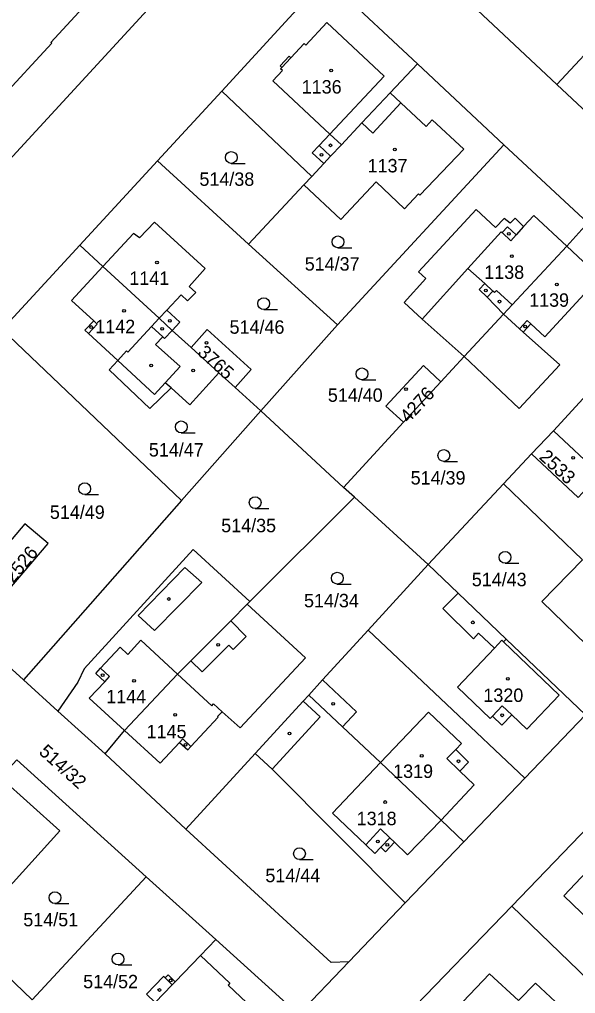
# Model space of a CAD drawing. Extents: x -679220 to -673243, y -1075091 to -1066557.
# Drawn here: x -675883.3 to -675812.8, y -1071990 to -1071866.6 of the extents above; entities that cross this region are included whole.
import ezdxf

# ---------------------------------------------------------------- set-up
doc = ezdxf.new("R2010")
doc.units = 0
for name, color, linetype in [('Hranice parcel', 7, 'Continuous'), ('Parcelní čísla', 7, 'Continuous'), ('Vnitřní kresba', 7, 'Continuous'), ('Značky budov', 7, 'Continuous'), ('Značky kultur', 7, 'Continuous')]:
    doc.layers.add(name, color=color, linetype=linetype)

msp = doc.modelspace()

# ---------------------------------------------------------------- linework, layer by layer
at = {"layer": 'Hranice parcel'}
for p, q in [((-675901.1, -1071902.37), (-675855.72, -1071853.08)), ((-675845.47, -1071862.48), (-675857.63, -1071875.7)), ((-675826.57, -1071864.15), (-675815.16, -1071874.86)), ((-675836.28, -1071875.93), (-675832.83, -1071872.25)), ((-675821.85, -1071882.53), (-675832.83, -1071872.25)), ((-675815.16, -1071874.86), (-675804.58, -1071884.78)), ((-675857.63, -1071875.7), (-675865.78, -1071884.56)), ((-675857.63, -1071875.7), (-675846.23, -1071886.54)), ((-675842.97, -1071905.34), (-675821.85, -1071882.53)), ((-675811.23, -1071892.4), (-675821.85, -1071882.53)), ((-675865.78, -1071884.56), (-675875.64, -1071895.21)), ((-675865.78, -1071884.56), (-675854.23, -1071895.09)), ((-675846.23, -1071886.54), (-675847.22, -1071887.6)), ((-675847.22, -1071887.6), (-675854.23, -1071895.09)), ((-675811.23, -1071892.4), (-675813.9, -1071895.36)), ((-675875.64, -1071895.21), (-675885.45, -1071905.91)), ((-675875.64, -1071895.21), (-675872.69, -1071897.92)), ((-675854.23, -1071895.09), (-675842.97, -1071905.34)), ((-675842.97, -1071905.34), (-675852.69, -1071916.2)), ((-675885.45, -1071905.91), (-675862.74, -1071927.57)), ((-675861.5, -1071908.21), (-675863.91, -1071906.02)), ((-675857.99, -1071911.4), (-675861.5, -1071908.21)), ((-675826.9, -1071909.35), (-675829.85, -1071912.55)), ((-675836.82, -1071915.62), (-675832.07, -1071910.45)), ((-675832.07, -1071910.45), (-675829.85, -1071912.55)), ((-675855.95, -1071913.25), (-675857.99, -1071911.4)), ((-675855.95, -1071913.25), (-675852.69, -1071916.2)), ((-675829.85, -1071912.55), (-675834.59, -1071917.67)), ((-675834.59, -1071917.67), (-675836.82, -1071915.62)), ((-675815.59, -1071918.73), (-675811.79, -1071914.67)), ((-675852.69, -1071916.2), (-675862.74, -1071927.57)), ((-675842.21, -1071925.93), (-675852.69, -1071916.2)), ((-675834.59, -1071917.67), (-675842.21, -1071925.93)), ((-675815.59, -1071918.73), (-675818.35, -1071921.68)), ((-675821.9, -1071925.48), (-675818.35, -1071921.68)), ((-675831.46, -1071935.7), (-675821.9, -1071925.48)), ((-675811.91, -1071935.09), (-675821.9, -1071925.48)), ((-675840.82, -1071927.14), (-675842.21, -1071925.93)), ((-675862.74, -1071927.57), (-675882.76, -1071950.27)), ((-675840.82, -1071927.14), (-675854.05, -1071940.37)), ((-675831.46, -1071935.7), (-675840.82, -1071927.14)), ((-675831.46, -1071935.7), (-675839.07, -1071944)), ((-675854.41, -1071940.72), (-675854.05, -1071940.37)), ((-675819.22, -1071962.75), (-675839.07, -1071944)), ((-675878.42, -1071954.27), (-675882.76, -1071950.27)), ((-675878.42, -1071954.27), (-675872.41, -1071959.68)), ((-675819.22, -1071962.75), (-675811.53, -1071954.74)), ((-675872.41, -1071959.68), (-675869.95, -1071956.71)), ((-675862.19, -1071969.22), (-675872.41, -1071959.68)), ((-675862.19, -1071969.22), (-675853.4, -1071959.63)), ((-675883.62, -1071960.42), (-675867.2, -1071975.24)), ((-675826.96, -1071970.82), (-675819.22, -1071962.75)), ((-675811.14, -1071968.85), (-675820.87, -1071978.95)), ((-675834.38, -1071978.55), (-675826.96, -1071970.82)), ((-675881.66, -1071990.83), (-675867.2, -1071975.24)), ((-675867.2, -1071975.24), (-675858.37, -1071983.2)), ((-675841.54, -1071986.02), (-675834.38, -1071978.55)), ((-675820.87, -1071978.95), (-675834.25, -1071992.83)), ((-675820.87, -1071978.95), (-675806.12, -1071993.2)), ((-675890.64, -1071982.25), (-675881.66, -1071990.83)), ((-675848.93, -1071993.73), (-675841.54, -1071986.02))]:
    msp.add_line(p, q, dxfattribs=at)
for points in [[(-675879.3, -1071869.55), (-675867.15, -1071856.4), (-675878.15, -1071846.32), (-675881.81, -1071850.32), (-675878.64, -1071853.22), (-675887.1, -1071862.37), (-675891.64, -1071858.18), (-675898.1, -1071865.18), (-675893.57, -1071869.37), (-675900, -1071876.33), (-675900.67, -1071875.72), (-675902.04, -1071877.21), (-675902.65, -1071876.64), (-675903.4, -1071877.45), (-675905.25, -1071875.74), (-675908.95, -1071879.75), (-675898.03, -1071889.82), (-675885.83, -1071876.61), (-675885.72, -1071876.72), (-675879.19, -1071869.65), (-675879.3, -1071869.55)], [(-675799.09, -1071857.6), (-675802.4, -1071861.16), (-675815.16, -1071874.86)], [(-675832.83, -1071872.25), (-675843.33, -1071862.41), (-675845.47, -1071862.48)], [(-675847.22, -1071887.6), (-675842.54, -1071891.96), (-675838.04, -1071887.22), (-675834.47, -1071890.62), (-675832.68, -1071888.72), (-675832.5, -1071888.9), (-675826.93, -1071883.08), (-675830.94, -1071879.34), (-675831.73, -1071880.18), (-675834.93, -1071877.19), (-675836.28, -1071875.93)], [(-675846.23, -1071886.54), (-675844.7, -1071884.9), (-675843.83, -1071883.97), (-675842.46, -1071882.51), (-675839.86, -1071879.74), (-675836.28, -1071875.93)], [(-675813.9, -1071895.36), (-675818.07, -1071891.47), (-675819.37, -1071892.88), (-675820.45, -1071891.79), (-675821.07, -1071892.46), (-675821.83, -1071891.83), (-675822.92, -1071893.01), (-675825.37, -1071890.69), (-675832.67, -1071898.6), (-675831.75, -1071899.45), (-675834.5, -1071902.5), (-675832.21, -1071904.61), (-675826.9, -1071909.35)], [(-675863.91, -1071906.02), (-675862.96, -1071904.98), (-675864.6, -1071903.45), (-675862.76, -1071901.53), (-675861.96, -1071902.26), (-675860.93, -1071901.22), (-675861.78, -1071900.46), (-675859.72, -1071898.19), (-675866.15, -1071892.33), (-675868.07, -1071894.31), (-675868.83, -1071893.73), (-675872.69, -1071897.92)], [(-675826.9, -1071909.35), (-675821.91, -1071903.95), (-675820.83, -1071902.79), (-675813.9, -1071895.36)], [(-675826.9, -1071909.35), (-675819.92, -1071915.91), (-675814.78, -1071910.39), (-675819.43, -1071906.26), (-675818.44, -1071905.2), (-675816.67, -1071906.85), (-675809.7, -1071899.29), (-675813.9, -1071895.36)], [(-675872.69, -1071897.92), (-675876.67, -1071902.23), (-675873.86, -1071904.83), (-675874.98, -1071905.99), (-675874.53, -1071906.4), (-675870.81, -1071909.84), (-675871.89, -1071911.01), (-675866.74, -1071915.93), (-675864.06, -1071913.32), (-675861.68, -1071915.47), (-675857.99, -1071911.4)], [(-675872.69, -1071897.92), (-675865.57, -1071904.49), (-675863.91, -1071906.02)], [(-675861.5, -1071908.21), (-675859.49, -1071905.93), (-675853.9, -1071910.96), (-675855.95, -1071913.25)], [(-675818.35, -1071921.68), (-675812.45, -1071927.19), (-675809.7, -1071924.24), (-675815.59, -1071918.73)], [(-675882.76, -1071950.27), (-675905.4, -1071929.7), (-675905.43, -1071927.64)], [(-675887.68, -1071936.49), (-675884.73, -1071939.01), (-675879.65, -1071933.04), (-675882.58, -1071930.53), (-675887.68, -1071936.49)], [(-675854.05, -1071940.37), (-675861.26, -1071933.8), (-675875.08, -1071948.91), (-675875.87, -1071950.6), (-675878.42, -1071954.27)], [(-675811.91, -1071935.09), (-675817.04, -1071940.36), (-675810, -1071947.2), (-675804.84, -1071941.89)], [(-675811.53, -1071954.74), (-675821.58, -1071945.14), (-675827.67, -1071939.33), (-675831.46, -1071935.7)], [(-675869.95, -1071956.71), (-675863.24, -1071949.57), (-675861.55, -1071947.87), (-675856.49, -1071942.81), (-675854.41, -1071940.72)], [(-675869.95, -1071956.71), (-675865.42, -1071960.85), (-675862.97, -1071958.21), (-675861.94, -1071959.17), (-675861.54, -1071958.73), (-675858.07, -1071955.01), (-675858.15, -1071954.93), (-675857.58, -1071954.34), (-675855.28, -1071956.35), (-675847, -1071947.5), (-675854.41, -1071940.72)], [(-675839.07, -1071944), (-675844.85, -1071950.31), (-675846.61, -1071952.22)], [(-675846.61, -1071952.22), (-675847.32, -1071953), (-675853.4, -1071959.63)], [(-675826.96, -1071970.82), (-675829.83, -1071968.06), (-675837.49, -1071960.77), (-675842.33, -1071956.24), (-675846.61, -1071952.22)], [(-675853.4, -1071959.63), (-675851.26, -1071961.6), (-675834.38, -1071978.55)], [(-675890.64, -1071982.25), (-675886.07, -1071976.54), (-675885.24, -1071977.29), (-675878.14, -1071969.43), (-675885.7, -1071962.68), (-675883.62, -1071960.42)], [(-675841.54, -1071986.02), (-675843.78, -1071986.09), (-675862.19, -1071969.22)], [(-675808.43, -1071971.5), (-675814.28, -1071977.65), (-675808.71, -1071982.95), (-675807.04, -1071984.47)], [(-675858.37, -1071983.2), (-675860.31, -1071985.21), (-675863.53, -1071988.54), (-675864.44, -1071987.66), (-675864.81, -1071988.05), (-675865, -1071987.87), (-675867.17, -1071990.12), (-675866.07, -1071991.18), (-675867.74, -1071992.91), (-675871.32, -1071997.22), (-675873.06, -1071999.04)], [(-675848.93, -1071993.73), (-675849.01, -1071991.65), (-675858.37, -1071983.2)], [(-675826.28, -1071996.85), (-675826.93, -1071997.58), (-675826.68, -1071997.8), (-675827.77, -1071998.48), (-675825.66, -1072000.44), (-675825.06, -1071999.32), (-675824.82, -1071999.54), (-675824.2, -1071998.83), (-675820.87, -1072001.92), (-675815.03, -1071995.66), (-675816.85, -1071993.94), (-675814.7, -1071991.66), (-675817.85, -1071988.7), (-675820, -1071990.89), (-675823.68, -1071987.53), (-675829.61, -1071993.73), (-675826.28, -1071996.85)]]:
    msp.add_lwpolyline(points, dxfattribs=at)
at = {"layer": 'Vnitřní kresba'}
for p, q in [((-675846.96, -1071869.88), (-675844.29, -1071867.01)), ((-675837.06, -1071873.8), (-675844.29, -1071867.01)), ((-675848.87, -1071871.49), (-675847.18, -1071869.68)), ((-675847.18, -1071869.68), (-675846.96, -1071869.88)), ((-675850.22, -1071872.5), (-675849.09, -1071871.28)), ((-675849.09, -1071871.28), (-675848.87, -1071871.49)), ((-675850, -1071872.71), (-675850.22, -1071872.5)), ((-675850, -1071872.71), (-675848.87, -1071871.49)), ((-675851.16, -1071874.39), (-675849.95, -1071873.09)), ((-675850.17, -1071872.89), (-675850, -1071872.71)), ((-675849.95, -1071873.09), (-675850.17, -1071872.89)), ((-675843.92, -1071881.15), (-675851.16, -1071874.39)), ((-675837.06, -1071873.8), (-675843.92, -1071881.15)), ((-675838.48, -1071881.06), (-675834.93, -1071877.19)), ((-675839.86, -1071879.74), (-675838.48, -1071881.06)), ((-675845.29, -1071882.61), (-675843.92, -1071881.15)), ((-675843.92, -1071881.15), (-675842.46, -1071882.51)), ((-675846.16, -1071883.53), (-675845.29, -1071882.61)), ((-675844.7, -1071884.9), (-675846.16, -1071883.53)), ((-675845.29, -1071882.61), (-675843.83, -1071883.97)), ((-675822.09, -1071893.64), (-675821.41, -1071892.9)), ((-675821.41, -1071892.9), (-675820.29, -1071893.91)), ((-675819.37, -1071892.88), (-675820.29, -1071893.91)), ((-675826.45, -1071898.19), (-675822.2, -1071893.54)), ((-675822.2, -1071893.54), (-675822.09, -1071893.64)), ((-675822.09, -1071893.64), (-675820.97, -1071894.66)), ((-675820.97, -1071894.66), (-675820.29, -1071893.91)), ((-675826.45, -1071898.19), (-675832.21, -1071904.61)), ((-675824.29, -1071900.08), (-675826.45, -1071898.19)), ((-675825.01, -1071900.85), (-675824.29, -1071900.08)), ((-675823.98, -1071901.81), (-675825.01, -1071900.85)), ((-675824.29, -1071900.08), (-675823.27, -1071901.04)), ((-675823.27, -1071901.04), (-675823.98, -1071901.81)), ((-675821.91, -1071903.95), (-675823.98, -1071901.81)), ((-675823.06, -1071901.23), (-675823.27, -1071901.04)), ((-675822.8, -1071900.95), (-675823.06, -1071901.23)), ((-675820.83, -1071902.79), (-675822.8, -1071900.95)), ((-675866.52, -1071905.53), (-675865.57, -1071904.49)), ((-675865.57, -1071904.49), (-675864.6, -1071903.45)), ((-675819.9, -1071905.82), (-675821.91, -1071903.95)), ((-675873.43, -1071905.22), (-675874.53, -1071906.4)), ((-675873.86, -1071904.83), (-675873.43, -1071905.22)), ((-675869.53, -1071908.79), (-675866.52, -1071905.53)), ((-675866.52, -1071905.53), (-675865.12, -1071906.82)), ((-675819.9, -1071905.82), (-675818.91, -1071904.76)), ((-675819.43, -1071906.26), (-675819.9, -1071905.82)), ((-675818.91, -1071904.76), (-675818.44, -1071905.2)), ((-675865.12, -1071906.82), (-675866.01, -1071907.79)), ((-675865.12, -1071906.82), (-675864.87, -1071907.06)), ((-675863.91, -1071906.02), (-675864.87, -1071907.06)), ((-675866.01, -1071907.79), (-675862.92, -1071910.6)), ((-675870.81, -1071909.84), (-675869.7, -1071908.63)), ((-675869.7, -1071908.63), (-675869.53, -1071908.79)), ((-675866.15, -1071914.14), (-675870.81, -1071909.84)), ((-675862.92, -1071910.6), (-675864.79, -1071912.65)), ((-675864.79, -1071912.65), (-675866.15, -1071914.14)), ((-675864.06, -1071913.32), (-675864.79, -1071912.65)), ((-675868.23, -1071942.14), (-675862.32, -1071936.05)), ((-675862.32, -1071936.05), (-675860.16, -1071937.96)), ((-675860.16, -1071937.96), (-675866.16, -1071944.06)), ((-675829.59, -1071941.27), (-675827.67, -1071939.33)), ((-675825.72, -1071945.08), (-675829.59, -1071941.27)), ((-675866.16, -1071944.06), (-675868.23, -1071942.14)), ((-675856.49, -1071942.81), (-675854.52, -1071944.78)), ((-675869.54, -1071947.06), (-675867.87, -1071945.26)), ((-675867.87, -1071945.26), (-675863.24, -1071949.57)), ((-675854.52, -1071944.78), (-675856.18, -1071946.43)), ((-675825.07, -1071944.39), (-675825.72, -1071945.08)), ((-675823.07, -1071946.27), (-675825.07, -1071944.39)), ((-675822.11, -1071945.26), (-675823.07, -1071946.27)), ((-675821.9, -1071945.46), (-675822.11, -1071945.26)), ((-675821.58, -1071945.14), (-675821.9, -1071945.46)), ((-675873, -1071948.81), (-675870.52, -1071946.15)), ((-675870.52, -1071946.15), (-675869.54, -1071947.06)), ((-675856.73, -1071945.88), (-675860.13, -1071949.28)), ((-675856.18, -1071946.43), (-675856.73, -1071945.88)), ((-675823.07, -1071946.27), (-675827.74, -1071951.23)), ((-675814.87, -1071952.23), (-675821.9, -1071945.46)), ((-675873.61, -1071949.47), (-675873, -1071948.81)), ((-675871.86, -1071949.87), (-675873, -1071948.81)), ((-675860.13, -1071949.28), (-675861.55, -1071947.87)), ((-675872.47, -1071950.53), (-675873.61, -1071949.47)), ((-675872.47, -1071950.53), (-675871.86, -1071949.87)), ((-675863.24, -1071949.57), (-675858.9, -1071953.6)), ((-675874.42, -1071952.63), (-675872.47, -1071950.53)), ((-675844.85, -1071950.31), (-675840.55, -1071954.34)), ((-675827.74, -1071951.23), (-675823.62, -1071955.2)), ((-675869.95, -1071956.71), (-675874.42, -1071952.63)), ((-675818.96, -1071956.55), (-675814.87, -1071952.23)), ((-675858.9, -1071953.6), (-675858.66, -1071953.34)), ((-675858.66, -1071953.34), (-675857.58, -1071954.34)), ((-675845.17, -1071954.96), (-675847.32, -1071953)), ((-675822.06, -1071953.58), (-675823.3, -1071954.88)), ((-675820.87, -1071954.72), (-675822.06, -1071953.58)), ((-675851.26, -1071961.6), (-675845.17, -1071954.96)), ((-675840.55, -1071954.34), (-675842.33, -1071956.24)), ((-675837.49, -1071960.77), (-675831.43, -1071954.39)), ((-675831.43, -1071954.39), (-675827.25, -1071958.37)), ((-675823.3, -1071954.88), (-675823.62, -1071955.2)), ((-675823.3, -1071954.88), (-675822.11, -1071956.02)), ((-675820.87, -1071954.72), (-675822.11, -1071956.02)), ((-675818.96, -1071956.55), (-675820.87, -1071954.72)), ((-675862.97, -1071958.21), (-675862.56, -1071957.77)), ((-675862.56, -1071957.77), (-675861.54, -1071958.73)), ((-675827.25, -1071958.37), (-675827.97, -1071959.12)), ((-675827.97, -1071959.12), (-675829.08, -1071960.26)), ((-675827.97, -1071959.12), (-675826.33, -1071960.7)), ((-675843.57, -1071967.17), (-675837.49, -1071960.77)), ((-675829.08, -1071960.26), (-675827.44, -1071961.85)), ((-675826.33, -1071960.7), (-675827.44, -1071961.85)), ((-675827.44, -1071961.85), (-675825.63, -1071963.59)), ((-675825.63, -1071963.59), (-675829.83, -1071968.06)), ((-675839.37, -1071971.19), (-675843.57, -1071967.17)), ((-675829.83, -1071968.06), (-675834.08, -1071972.46)), ((-675837.51, -1071969.17), (-675839.37, -1071971.19)), ((-675836.34, -1071970.3), (-675837.51, -1071969.17)), ((-675839.37, -1071971.19), (-675838.24, -1071972.28)), ((-675837.48, -1071971.49), (-675836.34, -1071970.3)), ((-675836.88, -1071972.06), (-675835.74, -1071970.87)), ((-675835.74, -1071970.87), (-675836.34, -1071970.3)), ((-675834.08, -1071972.46), (-675835.74, -1071970.87)), ((-675838.24, -1071972.28), (-675837.48, -1071971.49)), ((-675837.48, -1071971.49), (-675836.88, -1071972.06)), ((-675860.31, -1071985.21), (-675856.6, -1071988.73)), ((-675863.9, -1071988.93), (-675864.81, -1071988.05)), ((-675866.07, -1071991.18), (-675863.9, -1071988.93)), ((-675863.9, -1071988.93), (-675863.53, -1071988.54)), ((-675856.6, -1071988.73), (-675856.81, -1071988.95)), ((-675856.81, -1071988.95), (-675852.95, -1071992.62))]:
    msp.add_line(p, q, dxfattribs=at)
at = {"layer": 'Značky budov'}
for centre in [(-675843.77, -1071873.1), (-675843.85, -1071882.58), (-675844.98, -1071883.79), (-675835.69, -1071883.12), (-675821.22, -1071893.78), (-675820.86, -1071896.63), (-675865.84, -1071897.43), (-675824.14, -1071900.97), (-675815.15, -1071900.21), (-675870.02, -1071903.54), (-675822.41, -1071902.38), (-675864.22, -1071904.8), (-675874.19, -1071905.6), (-675865.18, -1071905.82), (-675819.16, -1071905.53), (-675859.55, -1071907.59), (-675866.57, -1071910.48), (-675861.24, -1071911.1), (-675834.27, -1071913.48), (-675813.08, -1071922.18), (-675864.33, -1071940.05), (-675825.8, -1071943.01), (-675858.1, -1071945.86), (-675872.73, -1071949.69), (-675868.75, -1071950.43), (-675821.35, -1071950.17), (-675843.5, -1071953.34), (-675863.53, -1071954.72), (-675822.09, -1071954.78), (-675849.05, -1071957.09), (-675862.22, -1071958.51), (-675832.28, -1071959.93), (-675827.61, -1071960.61), (-675836.91, -1071965.77), (-675837.84, -1071970.76), (-675836.64, -1071971.2), (-675864.11, -1071988.36), (-675865.54, -1071989.58)]:
    msp.add_circle(centre, 0.175, dxfattribs=at)
at = {"layer": 'Značky kultur'}
for p, q in [((-675856.42, -1071884.87), (-675854.67, -1071884.87)), ((-675842.9, -1071895.56), (-675841.15, -1071895.56)), ((-675852.31, -1071903.38), (-675850.56, -1071903.38)), ((-675839.86, -1071912.28), (-675838.11, -1071912.28)), ((-675862.76, -1071919), (-675861.01, -1071919)), ((-675829.48, -1071922.62), (-675827.73, -1071922.62)), ((-675875, -1071926.83), (-675873.25, -1071926.83)), ((-675853.4, -1071928.59), (-675851.65, -1071928.59)), ((-675821.71, -1071935.52), (-675819.96, -1071935.52)), ((-675842.98, -1071938.16), (-675841.23, -1071938.16)), ((-675847.78, -1071973.06), (-675846.03, -1071973.06)), ((-675878.78, -1071978.63), (-675877.03, -1071978.63)), ((-675870.78, -1071986.41), (-675869.03, -1071986.41))]:
    msp.add_line(p, q, dxfattribs=at)
for centre in [(-675856.42, -1071884.12), (-675842.9, -1071894.81), (-675852.31, -1071902.63), (-675839.86, -1071911.53), (-675862.76, -1071918.25), (-675829.48, -1071921.87), (-675875, -1071926.08), (-675853.4, -1071927.84), (-675821.71, -1071934.77), (-675842.98, -1071937.41), (-675847.78, -1071972.31), (-675878.78, -1071977.88), (-675870.78, -1071985.66)]:
    msp.add_circle(centre, 0.75, dxfattribs=at)

# ---------------------------------------------------------------- texts
at = {"layer": 'Parcelní čísla'}
for s, p in [('1136', (-675847.49, -1071876.02)), ('1137', (-675839.14, -1071886.01)), ('514/38', (-675860.46, -1071887.71)), ('514/37', (-675847.11, -1071898.45)), ('1138', (-675824.35, -1071899.5)), ('1141', (-675869.34, -1071900.26)), ('1139', (-675818.66, -1071903.03)), ('1142', (-675873.66, -1071906.38)), ('514/46', (-675856.64, -1071906.45)), ('514/40', (-675844.18, -1071915.07)), ('514/47', (-675866.87, -1071922)), ('514/39', (-675833.68, -1071925.55)), ('514/49', (-675879.42, -1071929.9)), ('514/35', (-675857.7, -1071931.59)), ('514/43', (-675825.93, -1071938.43)), ('514/34', (-675847.2, -1071941.1)), ('1320', (-675824.46, -1071953.09)), ('1144', (-675872.28, -1071953.26)), ('1145', (-675867.16, -1071957.69)), ('1319', (-675835.9, -1071962.72)), ('1318', (-675840.52, -1071968.7)), ('514/44', (-675852.1, -1071975.92)), ('514/51', (-675882.79, -1071981.51)), ('514/52', (-675875.2, -1071989.36))]:
    msp.add_text(s, height=1.7, dxfattribs=at).set_placement(p)
for s, rotation, p in [('3765', 318, (-675860.81, -1071908.99)), ('4276', 47, (-675833.97, -1071917.85)), ('2533', 317, (-675817.49, -1071922.19)), ('2526', 50, (-675884.07, -1071938.12)), ('514/32', 318, (-675880.92, -1071959.57))]:
    msp.add_text(s, height=1.7, rotation=rotation, dxfattribs=at).set_placement(p)

doc.saveas('drawing.dxf')
